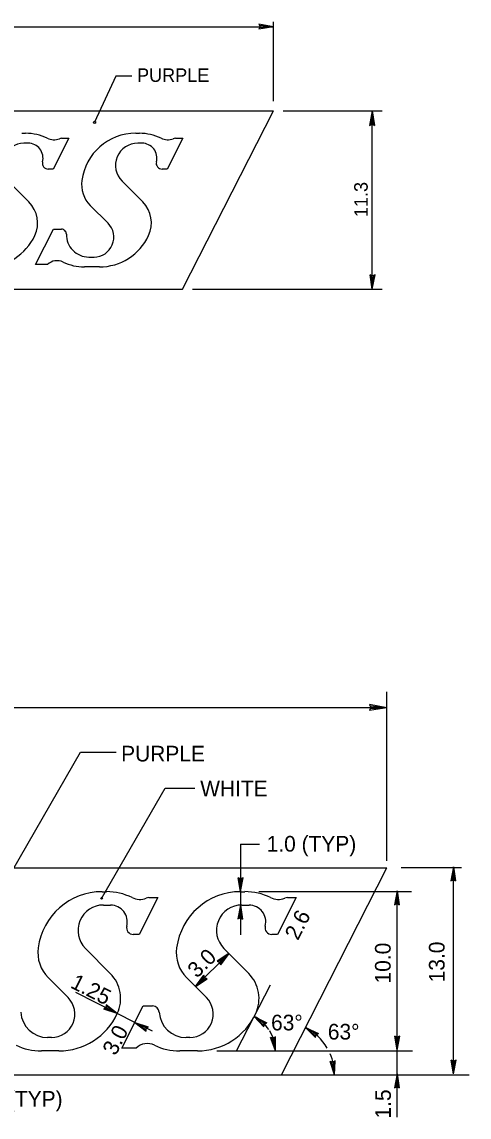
# Model space of a CAD drawing. Extents: x 10268197 to 10269179, y 2141503 to 2142677.
# Drawn here: x 10268891.94 to 10268911.92, y 2142094.22 to 2142143.17 of the extents above; entities that cross this region are included whole.
import ezdxf

# ---------------------------------------------------------------- set-up
doc = ezdxf.new("R2010")
doc.units = 0
for name, color, linetype in [('1', 7, 'Continuous'), ('20', 7, 'Continuous'), ('21', 7, 'Continuous'), ('Default', 7, 'Continuous'), ('GSBWFill', 7, 'Continuous')]:
    doc.layers.add(name, color=color, linetype=linetype)

msp = doc.modelspace()

# ---------------------------------------------------------------- linework, layer by layer
at = {"layer": '1'}
for p, q in [((10268903.175, 2142139.629), (10268903.175, 2142143.168)), ((10268883.975, 2142142.948), (10268903.175, 2142142.948)), ((10268896.14, 2142140.738), (10268895.186, 2142138.68)), ((10268896.843, 2142140.738), (10268896.14, 2142140.738)), ((10268903.618, 2142139.187), (10268908.042, 2142139.187)), ((10268907.599, 2142131.223), (10268907.599, 2142139.187)), ((10268899.56, 2142131.223), (10268908.042, 2142131.223)), ((10268878.648, 2142105.363), (10268908.253, 2142105.363)), ((10268903.538, 2142096.108), (10268908.253, 2142105.363)), ((10268895.518, 2142104.295), (10268895.716, 2142104.295)), ((10268898.007, 2142104.033), (10268897.175, 2142102.387)), ((10268897.614, 2142104.032), (10268898.007, 2142104.033)), ((10268901.704, 2142104.295), (10268901.903, 2142104.295)), ((10268904.195, 2142104.032), (10268903.363, 2142102.387)), ((10268903.802, 2142104.032), (10268904.195, 2142104.032)), ((10268895.581, 2142103.697), (10268895.9, 2142103.697)), ((10268901.768, 2142103.697), (10268902.088, 2142103.697)), ((10268897.175, 2142102.387), (10268896.914, 2142102.387)), ((10268903.363, 2142102.387), (10268903.101, 2142102.387)), ((10268894.774, 2142101.759), (10268895.888, 2142100.637)), ((10268900.962, 2142101.759), (10268902.076, 2142100.637)), ((10268893.997, 2142099.559), (10268893.11, 2142100.453)), ((10268900.185, 2142099.559), (10268899.297, 2142100.453)), ((10268896.407, 2142097.308), (10268897.357, 2142099.188)), ((10268897.357, 2142099.188), (10268897.778, 2142099.188)), ((10268893.254, 2142097.775), (10268893.083, 2142097.775)), ((10268899.442, 2142097.775), (10268899.271, 2142097.775)), ((10268893.593, 2142097.176), (10268892.805, 2142097.176)), ((10268897.042, 2142097.308), (10268896.407, 2142097.308)), ((10268899.78, 2142097.176), (10268898.992, 2142097.176)), ((10268878.065, 2142096.108), (10268903.538, 2142096.108))]:
    msp.add_line(p, q, dxfattribs=at)
msp.add_circle((10268895.187, 2142138.679), 0.0442, dxfattribs=at)
for centre, radius, start, end in [((10268895.581, 2142102.561), 1.137, 90, 224.7881), ((10268895.9, 2142102.949), 0.748, 345.4379, 90), ((10268901.768, 2142102.561), 1.137, 90, 224.7881), ((10268902.088, 2142102.949), 0.748, 345.4379, 90), ((10268896.913, 2142102.686), 0.299, 165.4379, 270), ((10268903.101, 2142102.686), 0.299, 165.4379, 270), ((10268893.254, 2142098.822), 1.047, 270, 44.7784), ((10268899.442, 2142098.822), 1.047, 270, 44.7784), ((10268897.777, 2142098.889), 0.299, 3.1643, 90), ((10268893.083, 2142098.971), 1.196, 183.1643, 270), ((10268899.27, 2142098.971), 1.196, 183.1643, 270)]:
    msp.add_arc(centre, radius, start, end, dxfattribs=at)
for centre, major_axis, start_param, end_param in [((10268895.517, 2142101.395), (0, 2.9), 0, 1.436562), ((10268895.715, 2142101.659), (0, 2.637), 5.830963, 6.283185), ((10268897.202, 2142104.742), (0, 0.791), 2.68937, 3.526171), ((10268897.614, 2142103.715), (0, 0.316), 0, 0.384579), ((10268901.704, 2142101.395), (0, 2.9), 0, 1.436562), ((10268901.903, 2142101.659), (0, 2.637), 5.830963, 6.283185), ((10268903.39, 2142104.742), (0, 0.791), 2.68937, 3.526171), ((10268903.802, 2142103.715), (0, 0.316), 0, 0.384579), ((10268894.22, 2142101.572), (0, 1.582), 1.436562, 2.356194), ((10268900.407, 2142101.572), (0, 1.582), 1.436562, 2.356194), ((10268894.778, 2142099.519), (0, -1.582), 1.133591, 2.356194), ((10268900.965, 2142099.519), (0, -1.582), 1.133591, 2.356194), ((10268893.592, 2142100.077), (0, -2.9), 0, 1.133591), ((10268899.78, 2142100.077), (0, -2.9), 0, 1.133591), ((10268892.805, 2142099.813), (0, -2.637), 5.836023, 6.283185), ((10268897.544, 2142096.77), (0, -0.738), 2.69443, 3.895387), ((10268898.992, 2142099.813), (0, -2.637), 5.836023, 6.283185)]:
    msp.add_ellipse(centre, major_axis=major_axis, ratio=0.992614, start_param=start_param, end_param=end_param, dxfattribs=at)
at = {"layer": '20'}
for p, q in [((10268908.253, 2142106.075), (10268908.253, 2142113.225)), ((10268908.253, 2142112.514), (10268861.216, 2142112.514)), ((10268890.784, 2142103.994), (10268894.555, 2142110.527)), ((10268894.555, 2142110.527), (10268896.144, 2142110.527)), ((10268895.5, 2142103.994), (10268898.342, 2142108.916)), ((10268898.342, 2142108.916), (10268899.661, 2142108.916)), ((10268901.704, 2142106.425), (10268901.705, 2142104.296)), ((10268901.704, 2142106.425), (10268902.562, 2142106.425)), ((10268908.253, 2142105.67), (10268908.253, 2142106.075)), ((10268911.584, 2142105.363), (10268908.892, 2142105.363)), ((10268911.221, 2142096.147), (10268911.221, 2142105.402)), ((10268901.705, 2142104.296), (10268901.705, 2142103.695)), ((10268902.533, 2142104.296), (10268909.357, 2142104.296)), ((10268908.706, 2142097.214), (10268908.706, 2142104.334)), ((10268901.705, 2142103.695), (10268901.704, 2142102.363)), ((10268899.694, 2142100.053), (10268901.186, 2142101.534)), ((10268901.535, 2142097.176), (10268903.044, 2142100.137)), ((10268896.2, 2142098.848), (10268894.341, 2142099.788)), ((10268896.985, 2142098.451), (10268896.2, 2142098.848)), ((10268897.77, 2142098.055), (10268896.985, 2142098.451)), ((10268900.652, 2142097.176), (10268904.082, 2142097.176)), ((10268904.082, 2142097.176), (10268909.396, 2142097.176)), ((10268908.706, 2142096.147), (10268908.706, 2142097.214)), ((10268903.538, 2142096.108), (10268911.924, 2142096.108)), ((10268908.706, 2142094.22), (10268908.706, 2142096.147))]:
    msp.add_line(p, q, dxfattribs=at)
msp.add_circle((10268895.5, 2142103.994), 0.0356, dxfattribs=at)
for centre, radius, start, end in [((10268901.535, 2142097.176), 1.73, 33.9529, 63.0014), ((10268901.535, 2142097.176), 1.73, 0, 31.4593), ((10268903.538, 2142096.108), 2.37, 30.3328, 63.0012), ((10268903.538, 2142096.108), 2.37, 360, 23.4794)]:
    msp.add_arc(centre, radius, start, end, dxfattribs=at)
at = {"layer": '21'}
for p, q in [((10268907.536, 2142112.526), (10268907.474, 2142112.39)), ((10268908.253, 2142112.514), (10268907.474, 2142112.39)), ((10268908.253, 2142112.514), (10268907.479, 2142112.664)), ((10268907.479, 2142112.664), (10268907.536, 2142112.526)), ((10268908.253, 2142112.514), (10268907.507, 2142112.461)), ((10268908.253, 2142112.514), (10268907.508, 2142112.592)), ((10268901.705, 2142104.296), (10268901.606, 2142104.919)), ((10268901.714, 2142104.87), (10268901.606, 2142104.919)), ((10268911.221, 2142105.402), (10268911.101, 2142104.782)), ((10268911.221, 2142105.402), (10268911.159, 2142104.806)), ((10268911.221, 2142105.402), (10268911.32, 2142104.778)), ((10268911.221, 2142105.402), (10268911.263, 2142104.805)), ((10268901.705, 2142104.296), (10268901.663, 2142104.893)), ((10268901.705, 2142104.296), (10268901.825, 2142104.915)), ((10268901.705, 2142104.296), (10268901.767, 2142104.892)), ((10268901.825, 2142104.915), (10268901.714, 2142104.87)), ((10268911.101, 2142104.782), (10268911.212, 2142104.828)), ((10268911.212, 2142104.828), (10268911.32, 2142104.778)), ((10268908.706, 2142104.334), (10268908.586, 2142103.714)), ((10268908.706, 2142104.334), (10268908.644, 2142103.738)), ((10268908.706, 2142104.334), (10268908.804, 2142103.71)), ((10268908.706, 2142104.334), (10268908.748, 2142103.737)), ((10268901.705, 2142103.695), (10268901.584, 2142103.076)), ((10268901.705, 2142103.695), (10268901.642, 2142103.099)), ((10268901.705, 2142103.695), (10268901.803, 2142103.072)), ((10268901.705, 2142103.695), (10268901.746, 2142103.098)), ((10268908.586, 2142103.714), (10268908.696, 2142103.76)), ((10268908.696, 2142103.76), (10268908.804, 2142103.71)), ((10268901.584, 2142103.076), (10268901.694, 2142103.121)), ((10268901.694, 2142103.121), (10268901.803, 2142103.072)), ((10268901.186, 2142101.534), (10268900.662, 2142101.183)), ((10268901.186, 2142101.534), (10268900.719, 2142101.159)), ((10268901.186, 2142101.534), (10268900.792, 2142101.084)), ((10268901.186, 2142101.534), (10268900.813, 2142101.025)), ((10268900.662, 2142101.183), (10268900.772, 2142101.137)), ((10268900.772, 2142101.137), (10268900.813, 2142101.025)), ((10268899.694, 2142100.053), (10268900.067, 2142100.563)), ((10268900.108, 2142100.451), (10268900.067, 2142100.563)), ((10268899.694, 2142100.053), (10268900.088, 2142100.504)), ((10268899.694, 2142100.053), (10268900.161, 2142100.429)), ((10268899.694, 2142100.053), (10268900.218, 2142100.404)), ((10268900.218, 2142100.404), (10268900.108, 2142100.451)), ((10268895.692, 2142099.116), (10268895.599, 2142099.041)), ((10268896.2, 2142098.848), (10268895.648, 2142099.08)), ((10268895.701, 2142099.235), (10268895.692, 2142099.116)), ((10268896.2, 2142098.848), (10268895.696, 2142099.173)), ((10268896.2, 2142098.848), (10268895.701, 2142099.235)), ((10268896.2, 2142098.848), (10268895.599, 2142099.041)), ((10268902.321, 2142098.719), (10268902.882, 2142098.43)), ((10268902.321, 2142098.719), (10268902.75, 2142098.255)), ((10268902.321, 2142098.719), (10268902.765, 2142098.316)), ((10268902.321, 2142098.719), (10268902.827, 2142098.399)), ((10268896.985, 2142098.451), (10268897.587, 2142098.258)), ((10268896.985, 2142098.451), (10268897.484, 2142098.064)), ((10268896.985, 2142098.451), (10268897.489, 2142098.127)), ((10268896.985, 2142098.451), (10268897.537, 2142098.219)), ((10268897.484, 2142098.064), (10268897.493, 2142098.183)), ((10268897.493, 2142098.183), (10268897.587, 2142098.258)), ((10268902.75, 2142098.255), (10268902.778, 2142098.371)), ((10268902.778, 2142098.371), (10268902.882, 2142098.43)), ((10268904.615, 2142098.221), (10268905.189, 2142097.959)), ((10268904.615, 2142098.221), (10268905.065, 2142097.778)), ((10268904.615, 2142098.221), (10268905.077, 2142097.839)), ((10268904.615, 2142098.221), (10268905.136, 2142097.926)), ((10268903.266, 2142097.178), (10268903.048, 2142097.771)), ((10268903.164, 2142097.743), (10268903.048, 2142097.771)), ((10268903.266, 2142097.178), (10268903.109, 2142097.756)), ((10268903.264, 2142097.809), (10268903.164, 2142097.743)), ((10268903.266, 2142097.178), (10268903.211, 2142097.775)), ((10268903.266, 2142097.178), (10268903.264, 2142097.809)), ((10268905.065, 2142097.778), (10268905.088, 2142097.895)), ((10268905.088, 2142097.895), (10268905.189, 2142097.959)), ((10268908.706, 2142097.214), (10268908.607, 2142097.838)), ((10268908.716, 2142097.788), (10268908.607, 2142097.838)), ((10268908.706, 2142097.214), (10268908.664, 2142097.811)), ((10268908.706, 2142097.214), (10268908.826, 2142097.834)), ((10268908.706, 2142097.214), (10268908.768, 2142097.81)), ((10268908.826, 2142097.834), (10268908.716, 2142097.788)), ((10268905.91, 2142096.106), (10268905.715, 2142096.706)), ((10268905.83, 2142096.674), (10268905.715, 2142096.706)), ((10268905.91, 2142096.106), (10268905.776, 2142096.689)), ((10268905.932, 2142096.737), (10268905.83, 2142096.674)), ((10268905.91, 2142096.106), (10268905.879, 2142096.704)), ((10268905.91, 2142096.106), (10268905.932, 2142096.737)), ((10268911.221, 2142096.147), (10268911.122, 2142096.77)), ((10268911.231, 2142096.721), (10268911.122, 2142096.77)), ((10268911.221, 2142096.147), (10268911.179, 2142096.744)), ((10268911.221, 2142096.147), (10268911.341, 2142096.767)), ((10268911.221, 2142096.147), (10268911.283, 2142096.743)), ((10268911.341, 2142096.767), (10268911.231, 2142096.721)), ((10268908.706, 2142096.147), (10268908.585, 2142095.527)), ((10268908.706, 2142096.147), (10268908.643, 2142095.551)), ((10268908.706, 2142096.147), (10268908.804, 2142095.523)), ((10268908.706, 2142096.147), (10268908.747, 2142095.55)), ((10268908.585, 2142095.527), (10268908.696, 2142095.573)), ((10268908.696, 2142095.573), (10268908.804, 2142095.523))]:
    msp.add_line(p, q, dxfattribs=at)
at = {"layer": 'Default'}
for p, q in [((10268902.58, 2142142.957), (10268902.528, 2142142.845)), ((10268903.175, 2142142.948), (10268902.528, 2142142.845)), ((10268903.175, 2142142.948), (10268902.532, 2142143.072)), ((10268902.532, 2142143.072), (10268902.58, 2142142.957)), ((10268903.175, 2142142.948), (10268902.556, 2142142.904)), ((10268903.175, 2142142.948), (10268902.557, 2142143.012)), ((10268877.937, 2142139.187), (10268903.175, 2142139.187)), ((10268899.117, 2142131.223), (10268903.175, 2142139.187)), ((10268907.599, 2142139.187), (10268907.475, 2142138.544)), ((10268907.599, 2142139.187), (10268907.535, 2142138.569)), ((10268907.599, 2142139.187), (10268907.702, 2142138.54)), ((10268907.599, 2142139.187), (10268907.643, 2142138.567)), ((10268907.475, 2142138.544), (10268907.589, 2142138.591)), ((10268907.589, 2142138.591), (10268907.702, 2142138.54)), ((10268891.936, 2142138.191), (10268892.104, 2142138.191)), ((10268892.216, 2142137.749), (10268892.027, 2142137.749)), ((10268894.04, 2142137.97), (10268893.337, 2142136.59)), ((10268893.709, 2142137.97), (10268894.04, 2142137.97)), ((10268897.024, 2142138.191), (10268897.192, 2142138.191)), ((10268897.304, 2142137.749), (10268897.114, 2142137.749)), ((10268899.129, 2142137.97), (10268898.425, 2142136.59)), ((10268898.796, 2142137.97), (10268899.129, 2142137.97)), ((10268893.337, 2142136.59), (10268893.116, 2142136.59)), ((10268898.425, 2142136.59), (10268898.204, 2142136.59)), ((10268891.322, 2142136.049), (10268892.25, 2142135.122)), ((10268896.41, 2142136.049), (10268897.338, 2142135.122)), ((10268895.785, 2142134.171), (10268894.989, 2142134.967)), ((10268892.546, 2142132.329), (10268893.349, 2142133.906)), ((10268893.349, 2142133.906), (10268893.705, 2142133.906)), ((10268893.083, 2142132.329), (10268892.546, 2142132.329)), ((10268894.921, 2142132.66), (10268895.159, 2142132.66)), ((10268895.397, 2142132.218), (10268894.732, 2142132.218)), ((10268907.599, 2142131.223), (10268907.496, 2142131.87)), ((10268907.609, 2142131.819), (10268907.496, 2142131.87)), ((10268907.599, 2142131.223), (10268907.556, 2142131.842)), ((10268907.599, 2142131.223), (10268907.724, 2142131.866)), ((10268907.599, 2142131.223), (10268907.664, 2142131.841)), ((10268907.724, 2142131.866), (10268907.609, 2142131.819)), ((10268877.35, 2142131.223), (10268899.117, 2142131.223))]:
    msp.add_line(p, q, dxfattribs=at)
for centre, radius, start, end in [((10268892.026, 2142136.753), 0.995, 90, 225), ((10268892.104, 2142135.978), 2.212, 64.0896, 90), ((10268892.216, 2142137.084), 0.664, 345.6915, 90), ((10268893.36, 2142138.565), 0.664, 244.0896, 292.0347), ((10268893.709, 2142137.704), 0.265, 90, 112.0347), ((10268897.024, 2142135.757), 2.433, 90, 172.3089), ((10268897.114, 2142136.753), 0.995, 90, 225), ((10268897.191, 2142135.978), 2.212, 64.0896, 90), ((10268897.304, 2142137.084), 0.664, 345.6915, 90), ((10268898.448, 2142138.565), 0.664, 244.0896, 292.0347), ((10268898.797, 2142137.704), 0.265, 90, 112.0347), ((10268893.116, 2142136.855), 0.265, 165.6915, 270), ((10268898.204, 2142136.855), 0.265, 165.6915, 270), ((10268895.928, 2142135.905), 1.327, 172.3089, 225), ((10268891.311, 2142134.183), 1.327, 334.95, 45), ((10268896.399, 2142134.183), 1.327, 334.95, 45), ((10268893.704, 2142133.684), 0.221, 358.6664, 90), ((10268895.159, 2142133.545), 0.885, 270, 45), ((10268890.309, 2142134.651), 2.433, 270, 334.95), ((10268894.921, 2142133.656), 0.995, 178.6665, 270), ((10268895.397, 2142134.651), 2.433, 270, 334.95), ((10268893.507, 2142131.877), 0.619, 64.3795, 133.1892), ((10268894.731, 2142134.43), 2.212, 244.3795, 270)]:
    msp.add_arc(centre, radius, start, end, dxfattribs=at)

# ---------------------------------------------------------------- texts
at = {"layer": '1'}
msp.add_text('PURPLE', height=0.6037, dxfattribs=at).set_placement((10268897.082, 2142140.487))
msp.add_text('11.3', height=0.6037, rotation=90, dxfattribs=at).set_placement((10268907.392, 2142134.445))
at = {"layer": '20'}
for s, p in [('PURPLE', (10268896.371, 2142110.115)), ('WHITE', (10268899.907, 2142108.557)), ('1.0 (TYP)', (10268902.876, 2142106.086)), ('63°', (10268903.073, 2142098.096)), ('63°', (10268905.61, 2142097.686)), ('.84 (TYP)', (10268889.75, 2142094.684))]:
    msp.add_text(s, height=0.7, dxfattribs=at).set_placement(p)
for s, rotation, p in [('2.6', 63.1678, (10268904.274, 2142102.082)), ('13.0', 90, (10268910.829, 2142100.242)), ('3.0', 44.7737, (10268899.76, 2142100.399)), ('10.0', 90, (10268908.418, 2142100.192)), ('1.25', 333.1861, (10268894.061, 2142100.027)), ('3.0', 63.1839, (10268896.127, 2142096.932)), ('1.5', 90, (10268908.427, 2142094.157))]:
    msp.add_text(s, height=0.7, rotation=rotation, dxfattribs=at).set_placement(p)
at = {"layer": 'GSBWFill'}
for s, p in [('reportName:OOCEA10', (10268895.337, 2142138.975)), ('tableTextHeight:0.0500', (10268895.337, 2142138.975)), ('plotScale:50', (10268895.338, 2142138.975)), ('letterPositions:2', (10268895.338, 2142138.975)), ('inchesDisplay:0', (10268895.338, 2142138.975))]:
    msp.add_text(s, height=0.000333, dxfattribs=at).set_placement(p)

doc.saveas('drawing.dxf')
